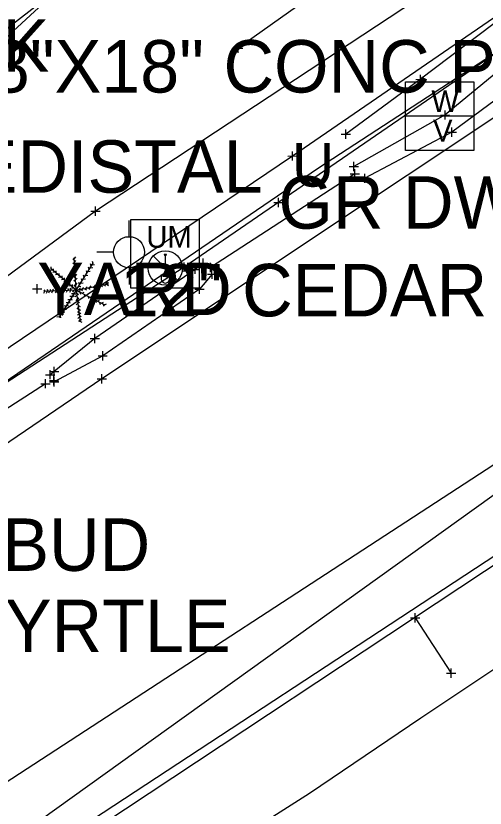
# Model space of a CAD drawing. Extents: x -1 to 1157254, y -1 to 2021979.
# Drawn here: x 1150616.3 to 1150680.9, y 2019818.7 to 2019927.5 of the extents above; entities that cross this region are included whole.
import ezdxf

# ---------------------------------------------------------------- set-up
doc = ezdxf.new("R2010")
doc.units = 0
for name, color, linetype in [('S_BUILDING_ANNOT', 7, 'Continuous'), ('S_CAL_CORNER', 7, 'Continuous'), ('S_CAL_CORNER_ANNOT', 7, 'Continuous'), ('S_CATCH_BASIN', 7, 'Continuous'), ('S_CONTOUR_ANNOT', 7, 'Continuous'), ('S_CONTOUR_MAJOR', 7, 'Continuous'), ('S_CONTOUR_MINOR', 7, 'Continuous'), ('S_CTL_TABLE', 7, 'Continuous'), ('S_CURB', 7, 'Continuous'), ('S_DRIVEWAY_ANNOT', 7, 'Continuous'), ('S_DROP_INLET', 7, 'Continuous'), ('S_DROP_INLET_ANNOT', 7, 'Continuous'), ('S_DTM_PAVEMENT', 7, 'Continuous'), ('S_EDGE_BITUMINOUS_ANNOT', 7, 'Continuous'), ('S_FENCE', 7, 'Continuous'), ('S_GAS_PUMP_ISLAND_ANNOT', 7, 'Continuous'), ('S_GATE', 7, 'Continuous'), ('S_GATE_ANNOT', 7, 'Continuous')]:
    doc.layers.add(name, color=color, linetype=linetype)

msp = doc.modelspace()

# ---------------------------------------------------------------- linework, layer by layer
at = {"layer": 'S_BUILDING_ANNOT'}
for p, q in [((1150674.7, 2019913.87), (1150675.97, 2019913.88)), ((1150675.34, 2019913.24), (1150675.33, 2019914.51)), ((1150675.33, 2019913.88), (1150675.33, 2019913.88)), ((1150676.27, 2019910.87), (1150676.27, 2019912.14)), ((1150675.63, 2019911.51), (1150676.91, 2019911.51)), ((1150676.27, 2019911.51), (1150676.27, 2019911.51)), ((1150654.37, 2019907.61), (1150654.36, 2019908.88)), ((1150653.73, 2019908.24), (1150655, 2019908.25)), ((1150654.37, 2019908.24), (1150654.37, 2019908.24)), ((1150662.79, 2019906.17), (1150662.78, 2019907.44)), ((1150662.15, 2019906.81), (1150663.42, 2019906.81)), ((1150662.78, 2019906.81), (1150662.78, 2019906.81)), ((1150662.93, 2019905.14), (1150662.93, 2019906.42)), ((1150662.3, 2019905.78), (1150663.57, 2019905.78)), ((1150662.93, 2019905.78), (1150662.93, 2019905.78)), ((1150663.66, 2019905.17), (1150664.93, 2019905.18)), ((1150664.3, 2019904.54), (1150664.29, 2019905.81)), ((1150664.29, 2019905.18), (1150664.29, 2019905.18)), ((1150652.45, 2019901.24), (1150652.44, 2019902.51)), ((1150627.27, 2019900.02), (1150627.27, 2019901.29)), ((1150651.81, 2019901.87), (1150653.08, 2019901.88)), ((1150652.44, 2019901.87), (1150652.44, 2019901.87)), ((1150626.64, 2019900.66), (1150627.91, 2019900.66)), ((1150627.27, 2019900.66), (1150627.27, 2019900.66)), ((1150639.49, 2019892.36), (1150639.49, 2019893.64)), ((1150640.97, 2019892.05), (1150640.96, 2019893.32)), ((1150641.43, 2019893.52), (1150642.71, 2019893.52)), ((1150642.07, 2019892.88), (1150642.07, 2019894.15)), ((1150642.07, 2019893.52), (1150642.07, 2019893.52)), ((1150643.07, 2019892.29), (1150643.07, 2019893.56)), ((1150638.85, 2019893), (1150640.13, 2019893)), ((1150639.49, 2019893), (1150639.49, 2019893)), ((1150640.33, 2019892.68), (1150641.6, 2019892.68)), ((1150640.96, 2019892.68), (1150640.96, 2019892.68)), ((1150642.43, 2019892.93), (1150643.7, 2019892.93)), ((1150643.07, 2019892.93), (1150643.07, 2019892.93)), ((1150643.3, 2019891.37), (1150643.29, 2019892.64)), ((1150642.66, 2019892.01), (1150643.93, 2019892.01)), ((1150643.3, 2019892.01), (1150643.3, 2019892.01)), ((1150618.62, 2019890), (1150619.9, 2019890)), ((1150619.26, 2019889.37), (1150619.26, 2019890.64)), ((1150619.26, 2019890), (1150619.26, 2019890)), ((1150640.93, 2019889.97), (1150642.21, 2019889.98)), ((1150641.57, 2019889.34), (1150641.57, 2019890.61)), ((1150641.57, 2019889.97), (1150641.57, 2019889.97)), ((1150627.18, 2019882.56), (1150627.18, 2019883.83)), ((1150626.54, 2019883.2), (1150627.81, 2019883.2)), ((1150627.18, 2019883.2), (1150627.18, 2019883.2)), ((1150628.27, 2019880.18), (1150628.27, 2019881.46)), ((1150627.63, 2019880.82), (1150628.9, 2019880.82)), ((1150628.27, 2019880.82), (1150628.27, 2019880.82)), ((1150621.58, 2019878.03), (1150621.58, 2019879.3)), ((1150620.4, 2019878.22), (1150621.68, 2019878.22)), ((1150620.94, 2019878.66), (1150622.22, 2019878.67)), ((1150621.04, 2019877.59), (1150621.04, 2019878.86)), ((1150621.04, 2019878.22), (1150621.04, 2019878.22)), ((1150621.57, 2019876.79), (1150621.56, 2019878.06)), ((1150621.58, 2019878.67), (1150621.58, 2019878.67)), ((1150628.16, 2019877.01), (1150628.15, 2019878.28)), ((1150619.78, 2019876.98), (1150621.05, 2019876.98)), ((1150620.42, 2019876.35), (1150620.41, 2019877.62)), ((1150620.42, 2019876.98), (1150620.42, 2019876.98)), ((1150620.93, 2019877.42), (1150622.2, 2019877.43)), ((1150620.95, 2019877.26), (1150622.23, 2019877.26)), ((1150621.57, 2019877.42), (1150621.57, 2019877.42)), ((1150621.59, 2019876.62), (1150621.59, 2019877.9)), ((1150621.59, 2019877.26), (1150621.59, 2019877.26)), ((1150627.52, 2019877.64), (1150628.79, 2019877.65)), ((1150628.16, 2019877.65), (1150628.16, 2019877.65)), ((1150671.22, 2019844.21), (1150671.21, 2019845.48)), ((1150670.58, 2019844.84), (1150671.85, 2019844.85)), ((1150671.22, 2019844.85), (1150671.22, 2019844.85)), ((1150676.19, 2019836.6), (1150676.19, 2019837.87)), ((1150675.55, 2019837.24), (1150676.82, 2019837.24)), ((1150676.19, 2019837.24), (1150676.19, 2019837.24))]:
    msp.add_line(p, q, dxfattribs=at)
at = {"layer": 'S_CAL_CORNER'}
for p, q in [((1150635.22, 2019894.53), (1150638.56, 2019891.19)), ((1150636.73, 2019894.75), (1150637.05, 2019894.75)), ((1150636.89, 2019892.86), (1150636.89, 2019894.6)), ((1150636.89, 2019892.86), (1150636.89, 2019891.81)), ((1150636.29, 2019891.96), (1150636.29, 2019891.78)), ((1150637.49, 2019891.96), (1150637.49, 2019891.74))]:
    msp.add_line(p, q, dxfattribs=at)
msp.add_lwpolyline([(1150632.12, 2019899.52), (1150641.54, 2019899.52), (1150641.54, 2019890.11), (1150632.12, 2019890.11)], close=True, dxfattribs=at)
msp.add_circle((1150636.89, 2019892.86), 2.36, dxfattribs=at)
for centre, radius, start, end in [((1150636.89, 2019894.75), 0.156, 180, 0), ((1150636.71, 2019892.36), 0.58, 223.1344, 287.472), ((1150637.06, 2019892.36), 0.58, 252.528, 316.8656)]:
    msp.add_arc(centre, radius, start, end, dxfattribs=at)
msp.add_ellipse((1150636.89, 2019891.62), major_axis=(0, -0.82), ratio=0.744362, start_param=4.519801, end_param=8.000179, dxfattribs=at)
at = {"layer": 'S_CAL_CORNER_ANNOT'}
for points in [[(1150827.62, 2020008.19), (1150733.09, 2019947.48), (1150628.16, 2019877.65), (1150500.75, 2019790.99), (1150424.78, 2019737.67), (1150355.4, 2019749.66)], [(1150682.05, 2019865.85), (1150601.54, 2019813.47), (1150510.58, 2019743.97), (1150405.28, 2019665.92), (1150310.69, 2019593.56), (1150188.92, 2019499.64), (1150039.45, 2019388.15), (1149962.15, 2019331.17), (1149944.63, 2019319.08), (1149774.15, 2019191.52), (1149712.73, 2019145.6), (1149665.81, 2019108.74), (1149605.46, 2019057.66), (1149527.46, 2018983.58), (1149450.12, 2018902.93), (1149278.32, 2018738.82), (1149257.2, 2018716.38), (1149237.23, 2018691.25), (1149165.09, 2018617.77), (1149125.26, 2018579.57), (1149069.5, 2018523.84), (1149012.03, 2018473.77), (1148938.88, 2018408.55)]]:
    msp.add_lwpolyline(points, dxfattribs=at)
at = {"layer": 'S_CATCH_BASIN'}
for p, q in [((1150631.89, 2019897.15), (1150631.89, 2019899.39)), ((1150629.79, 2019895.02), (1150627.47, 2019895.02)), ((1150631.96, 2019890.6), (1150631.96, 2019892.93))]:
    msp.add_line(p, q, dxfattribs=at)
msp.add_circle((1150631.89, 2019895.04), 2.13, dxfattribs=at)
at = {"layer": 'S_CONTOUR_ANNOT'}
for p, q in [((1150669.9, 2019918.44), (1150679.31, 2019918.44)), ((1150669.9, 2019909.02), (1150669.9, 2019918.44)), ((1150679.31, 2019918.44), (1150679.31, 2019909.02)), ((1150669.9, 2019913.75), (1150679.31, 2019913.75)), ((1150679.31, 2019909.02), (1150669.9, 2019909.02))]:
    msp.add_line(p, q, dxfattribs=at)
for points in [[(1150857.08, 2020031.73), (1150832.22, 2020016.43), (1150747.37, 2019963.08), (1150692.94, 2019929.63), (1150639.49, 2019893), (1150583.9, 2019856.96), (1150484.25, 2019790.85), (1150433.08, 2019750.74), (1150355.8, 2019695.65), (1150341.28, 2019681.73), (1150287.94, 2019641.18), (1150216.41, 2019587.25), (1150034.4, 2019445.88), (1149979.98, 2019405.6), (1149934.92, 2019374.11), (1149784.56, 2019258.12)], [(1150776.08, 2020000.06), (1150711.77, 2019956.26), (1150627.27, 2019900.66), (1150578.77, 2019864.96), (1150479.12, 2019798.68), (1150423.47, 2019764.16), (1150358.5, 2019722.73), (1150313.96, 2019690.01), (1150273.95, 2019661.03), (1150225.64, 2019623.26), (1150033.5, 2019468.9), (1149971.69, 2019423.78), (1149931.59, 2019393.98), (1149688.42, 2019230.92)]]:
    msp.add_lwpolyline(points, dxfattribs=at)
at = {"layer": 'S_CONTOUR_MINOR'}
msp.add_lwpolyline([(1150622.8, 2019931.71), (1150421.67, 2019776.18)], dxfattribs=at)
at = {"layer": 'S_CTL_TABLE'}
for p, q in [((1150646.88, 2019922.42), (1150646.88, 2019923.7)), ((1150646.25, 2019923.06), (1150647.52, 2019923.06)), ((1150646.88, 2019923.06), (1150646.88, 2019923.06)), ((1150671.94, 2019918.14), (1150671.94, 2019919.41)), ((1150671.3, 2019918.77), (1150672.58, 2019918.78)), ((1150671.94, 2019918.78), (1150671.94, 2019918.78)), ((1150661.69, 2019910.6), (1150661.69, 2019911.88)), ((1150661.05, 2019911.24), (1150662.33, 2019911.24)), ((1150661.69, 2019911.24), (1150661.69, 2019911.24))]:
    msp.add_line(p, q, dxfattribs=at)
at = {"layer": 'S_CURB'}
for p, q in [((1150624.37, 2019894.16), (1150624.56, 2019894.39)), ((1150624.37, 2019893.91), (1150624.15, 2019894.11)), ((1150624.41, 2019893.35), (1150624.18, 2019893.55)), ((1150624.63, 2019889.83), (1150624.36, 2019894.27)), ((1150624.4, 2019893.68), (1150624.59, 2019893.92)), ((1150624.43, 2019893.08), (1150624.62, 2019893.32)), ((1150624.63, 2019889.83), (1150626.97, 2019893.52)), ((1150626.7, 2019893.14), (1150626.61, 2019893.43)), ((1150626.83, 2019893.3), (1150627.13, 2019893.35)), ((1150626.94, 2019893.48), (1150626.85, 2019893.77)), ((1150621.35, 2019892.57), (1150621.05, 2019892.53)), ((1150624.63, 2019889.83), (1150621.16, 2019892.74)), ((1150621.2, 2019892.72), (1150621.2, 2019893.02)), ((1150621.69, 2019892.3), (1150621.39, 2019892.27)), ((1150621.52, 2019892.47), (1150621.52, 2019892.77)), ((1150621.87, 2019892.17), (1150621.87, 2019892.47)), ((1150622.29, 2019891.81), (1150622.29, 2019892.11)), ((1150624.43, 2019892.77), (1150624.21, 2019892.97)), ((1150624.46, 2019892.12), (1150624.24, 2019892.32)), ((1150624.47, 2019892.37), (1150624.66, 2019892.61)), ((1150626.11, 2019892.17), (1150626.02, 2019892.46)), ((1150626.27, 2019892.39), (1150626.56, 2019892.43)), ((1150626.4, 2019892.69), (1150626.31, 2019892.98)), ((1150626.59, 2019892.88), (1150626.89, 2019892.92)), ((1150622.05, 2019891.98), (1150621.76, 2019891.95)), ((1150622.51, 2019891.6), (1150622.21, 2019891.58)), ((1150622.87, 2019891.27), (1150622.58, 2019891.25)), ((1150622.7, 2019891.48), (1150622.7, 2019891.78)), ((1150623.02, 2019891.2), (1150623.02, 2019891.5)), ((1150623.39, 2019890.9), (1150623.39, 2019891.2)), ((1150624.5, 2019891.52), (1150624.27, 2019891.72)), ((1150624.54, 2019890.96), (1150624.31, 2019891.15)), ((1150624.53, 2019891.81), (1150624.72, 2019892.04)), ((1150624.55, 2019891.24), (1150624.74, 2019891.47)), ((1150625.43, 2019891.12), (1150625.35, 2019891.4)), ((1150625.6, 2019891.33), (1150625.89, 2019891.37)), ((1150625.73, 2019891.61), (1150625.64, 2019891.89)), ((1150625.94, 2019891.85), (1150626.24, 2019891.89)), ((1150621.6, 2019889.7), (1150621.43, 2019889.94)), ((1150622.17, 2019889.71), (1150622, 2019889.96)), ((1150622.72, 2019889.75), (1150622.55, 2019890)), ((1150623.21, 2019891.01), (1150622.91, 2019890.98)), ((1150623.2, 2019889.76), (1150623.03, 2019890.01)), ((1150623.55, 2019890.71), (1150623.25, 2019890.69)), ((1150623.64, 2019889.8), (1150623.47, 2019890.05)), ((1150623.92, 2019890.41), (1150623.62, 2019890.39)), ((1150623.76, 2019890.59), (1150623.76, 2019890.89)), ((1150623.97, 2019889.84), (1150623.8, 2019890.09)), ((1150624.28, 2019890.12), (1150623.98, 2019890.09)), ((1150624.11, 2019890.28), (1150624.11, 2019890.58)), ((1150624.55, 2019890.34), (1150624.33, 2019890.54)), ((1150624.57, 2019890.57), (1150624.76, 2019890.8)), ((1150624.63, 2019889.83), (1150629.05, 2019890.7)), ((1150625.07, 2019890.59), (1150624.98, 2019890.87)), ((1150624.98, 2019890.32), (1150625.27, 2019890.37)), ((1150625, 2019889.92), (1150625.21, 2019890.14)), ((1150625.25, 2019889.95), (1150625.5, 2019889.79)), ((1150625.26, 2019890.79), (1150625.56, 2019890.83)), ((1150625.4, 2019889.98), (1150625.61, 2019890.2)), ((1150625.76, 2019890.03), (1150626.02, 2019889.87)), ((1150625.93, 2019890.08), (1150626.13, 2019890.3)), ((1150626.28, 2019890.14), (1150626.53, 2019889.98)), ((1150626.5, 2019890.21), (1150626.7, 2019890.43)), ((1150626.89, 2019890.27), (1150627.14, 2019890.11)), ((1150627.13, 2019890.35), (1150627.33, 2019890.57)), ((1150627.47, 2019890.38), (1150627.72, 2019890.22)), ((1150627.73, 2019890.44), (1150627.93, 2019890.66)), ((1150627.98, 2019890.49), (1150628.23, 2019890.33)), ((1150628.21, 2019890.54), (1150628.41, 2019890.77)), ((1150628.4, 2019890.58), (1150628.65, 2019890.42)), ((1150628.65, 2019890.63), (1150628.86, 2019890.86)), ((1150628.81, 2019890.64), (1150629.06, 2019890.48)), ((1150628.88, 2019890.69), (1150629.08, 2019890.91)), ((1150620.26, 2019889.62), (1150620.13, 2019889.35)), ((1150624.63, 2019889.83), (1150620.18, 2019889.62)), ((1150620.41, 2019889.64), (1150620.24, 2019889.89)), ((1150620.61, 2019889.65), (1150620.48, 2019889.38)), ((1150620.8, 2019889.67), (1150620.63, 2019889.92)), ((1150620.95, 2019889.67), (1150620.82, 2019889.4)), ((1150621.2, 2019889.67), (1150621.03, 2019889.92)), ((1150621.37, 2019889.68), (1150621.24, 2019889.41)), ((1150621.88, 2019889.7), (1150621.75, 2019889.44)), ((1150624.63, 2019889.83), (1150622.25, 2019886.06)), ((1150622.44, 2019889.73), (1150622.31, 2019889.46)), ((1150622.93, 2019889.75), (1150622.79, 2019889.48)), ((1150623.4, 2019889.78), (1150623.26, 2019889.51)), ((1150623.85, 2019889.78), (1150623.72, 2019889.51)), ((1150624.06, 2019888.97), (1150623.76, 2019888.94)), ((1150624.3, 2019889.34), (1150624, 2019889.3)), ((1150624.24, 2019889.8), (1150624.11, 2019889.53)), ((1150624.21, 2019889.18), (1150624.28, 2019888.89)), ((1150624.42, 2019889.51), (1150624.5, 2019889.22)), ((1150624.69, 2019889.16), (1150624.49, 2019888.93)), ((1150624.63, 2019889.83), (1150628.54, 2019887.79)), ((1150624.63, 2019889.83), (1150625.16, 2019885.46)), ((1150624.71, 2019889.41), (1150624.96, 2019889.25)), ((1150624.74, 2019888.85), (1150625, 2019888.7)), ((1150624.96, 2019889.65), (1150625.22, 2019889.79)), ((1150625.14, 2019889.56), (1150625.21, 2019889.27)), ((1150625.43, 2019889.43), (1150625.7, 2019889.57)), ((1150625.72, 2019889.25), (1150625.79, 2019888.96)), ((1150625.99, 2019889.12), (1150626.25, 2019889.26)), ((1150626.25, 2019888.98), (1150626.32, 2019888.68)), ((1150626.54, 2019888.84), (1150626.81, 2019888.98)), ((1150623.53, 2019888.11), (1150623.23, 2019888.07)), ((1150623.42, 2019887.9), (1150623.49, 2019887.61)), ((1150623.78, 2019888.52), (1150623.49, 2019888.49)), ((1150623.67, 2019888.32), (1150623.75, 2019888.03)), ((1150623.93, 2019888.74), (1150624.01, 2019888.45)), ((1150624.75, 2019888.58), (1150624.56, 2019888.35)), ((1150624.84, 2019888.02), (1150624.64, 2019887.79)), ((1150624.83, 2019888.29), (1150625.08, 2019888.13)), ((1150626.78, 2019888.71), (1150626.85, 2019888.41)), ((1150627.03, 2019888.58), (1150627.29, 2019888.72)), ((1150627.31, 2019888.41), (1150627.38, 2019888.12)), ((1150627.56, 2019888.31), (1150627.83, 2019888.45)), ((1150627.83, 2019888.15), (1150627.9, 2019887.86)), ((1150628.11, 2019888.03), (1150628.38, 2019888.17)), ((1150628.32, 2019887.9), (1150628.39, 2019887.61)), ((1150628.5, 2019887.83), (1150628.77, 2019887.97)), ((1150622.73, 2019886.86), (1150622.43, 2019886.83)), ((1150622.97, 2019887.23), (1150622.67, 2019887.2)), ((1150622.89, 2019887.05), (1150622.96, 2019886.76)), ((1150623.27, 2019887.69), (1150622.97, 2019887.65)), ((1150623.13, 2019887.43), (1150623.21, 2019887.14)), ((1150624.91, 2019887.45), (1150624.71, 2019887.22)), ((1150624.97, 2019886.99), (1150624.78, 2019886.76)), ((1150624.89, 2019887.74), (1150625.15, 2019887.58)), ((1150624.96, 2019887.23), (1150625.22, 2019887.07)), ((1150625, 2019886.8), (1150625.25, 2019886.64)), ((1150622.28, 2019886.15), (1150621.98, 2019886.11)), ((1150622.48, 2019886.45), (1150622.18, 2019886.41)), ((1150622.4, 2019886.31), (1150622.48, 2019886.02)), ((1150622.63, 2019886.65), (1150622.7, 2019886.36)), ((1150625.01, 2019886.61), (1150624.82, 2019886.38)), ((1150625.07, 2019886.17), (1150624.87, 2019885.94)), ((1150625.12, 2019885.75), (1150624.92, 2019885.52)), ((1150625.04, 2019886.39), (1150625.3, 2019886.23)), ((1150625.11, 2019885.93), (1150625.36, 2019885.77)), ((1150625.14, 2019885.58), (1150625.4, 2019885.43))]:
    msp.add_line(p, q, dxfattribs=at)
at = {"layer": 'S_DRIVEWAY_ANNOT'}
for points in [[(1150855.79, 2020029.67), (1150831.35, 2020015.2), (1150787.83, 2019987.87), (1150747.94, 2019962.05), (1150731.32, 2019950.7), (1150693.75, 2019928.98), (1150675.33, 2019913.88), (1150662.78, 2019906.81)], [(1150856.47, 2020028.31), (1150832.96, 2020013.32), (1150788.5, 2019986.18), (1150749.93, 2019959.55), (1150733, 2019948.71), (1150695.21, 2019925.46), (1150676.27, 2019911.51), (1150664.29, 2019905.18)], [(1150642.07, 2019893.52), (1150640.96, 2019892.68), (1150627.18, 2019883.2), (1150621.58, 2019878.67), (1150621.04, 2019878.22)], [(1150643.3, 2019892.01), (1150641.57, 2019889.97), (1150628.27, 2019880.82), (1150621.59, 2019877.26), (1150621.57, 2019877.42)]]:
    msp.add_lwpolyline(points, dxfattribs=at)
at = {"layer": 'S_DROP_INLET'}
for points in [[(1150831.49, 2020022.11), (1150729.58, 2019954.73), (1150690.81, 2019927.93), (1150657.92, 2019906.59), (1150452.8, 2019766.7), (1150415.16, 2019745.86)], [(1150852.18, 2019973.05), (1150778.54, 2019928.45), (1150770.16, 2019919.18), (1150703.8, 2019877.29), (1150608.63, 2019809.12), (1150513.43, 2019739.89), (1150405.92, 2019663.65), (1150352.2, 2019622.72), (1150343.81, 2019614.74), (1150336.72, 2019606.98), (1150314.89, 2019591.84), (1150193.25, 2019498.28), (1150112.69, 2019435.49), (1150059.59, 2019406.16), (1150037.88, 2019389.79), (1149962.99, 2019329.91), (1149914.05, 2019297.4), (1149863.26, 2019256.98)], [(1150853.56, 2019969.99), (1150781.71, 2019924.44), (1150774.41, 2019914.43), (1150697.13, 2019863.12), (1150609.24, 2019805.57), (1150516.58, 2019735.98), (1150408.74, 2019655.56), (1150359.48, 2019622.09), (1150352.77, 2019615.32), (1150355.2, 2019603.6), (1150359.35, 2019593.87)]]:
    msp.add_lwpolyline(points, dxfattribs=at)
at = {"layer": 'S_DROP_INLET_ANNOT'}
for points in [[(1150662.93, 2019905.78), (1150643.07, 2019892.93)], [(1150620.42, 2019876.98), (1150600.25, 2019864)]]:
    msp.add_lwpolyline(points, dxfattribs=at)
at = {"layer": 'S_DTM_PAVEMENT'}
msp.add_lwpolyline([(1150671.22, 2019844.85), (1150676.19, 2019837.24)], dxfattribs=at)
at = {"layer": 'S_EDGE_BITUMINOUS_ANNOT'}
for points in [[(1150780.18, 2020046.65), (1150731.01, 2020016.6), (1150711.37, 2019980.59), (1150665.89, 2019975.73), (1150652.68, 2019953.36), (1150630.56, 2019938.88), (1150601.87, 2019912.49)], [(1150789.87, 2020023.58), (1150749.39, 2019989.07), (1150720.66, 2019965.01), (1150679.31, 2019951.64), (1150664.04, 2019935.25), (1150646.88, 2019923.06)], [(1150798.77, 2020003.69), (1150757.39, 2019975.96), (1150726.02, 2019955.41), (1150691.87, 2019933.84), (1150671.94, 2019918.78), (1150661.69, 2019911.24)]]:
    msp.add_lwpolyline(points, dxfattribs=at)
at = {"layer": 'S_FENCE'}
for points in [[(1150830.5, 2020023.61), (1150689.74, 2019932.52), (1150654.37, 2019908.24), (1150454.61, 2019773.54), (1150421.5, 2019756.1), (1150406.6, 2019759.37)], [(1150775.16, 2019913.88), (1150697.15, 2019862.05), (1150611.54, 2019805.47), (1150516.86, 2019735.37), (1150402.98, 2019659.79), (1150352.98, 2019622.15), (1150350.25, 2019606.72), (1150331.34, 2019598.55), (1150196.24, 2019490.87), (1150043.62, 2019380.11), (1149966.77, 2019324.72), (1149934.21, 2019308.48), (1149916.33, 2019289.12), (1149866.68, 2019250.91)]]:
    msp.add_lwpolyline(points, dxfattribs=at)
at = {"layer": 'S_GAS_PUMP_ISLAND_ANNOT'}
msp.add_lwpolyline([(1150475.18, 2019729.75), (1150486.94, 2019739.18), (1150527.36, 2019744.97), (1150530.87, 2019745.39), (1150533.26, 2019748.12), (1150533.67, 2019750.16), (1150547.31, 2019784.88), (1150559.34, 2019793.54), (1150571.53, 2019802.29), (1150616.62, 2019786.84), (1150617.46, 2019781.87), (1150618.41, 2019777.23), (1150619.34, 2019771.87), (1150620.18, 2019766.9), (1150620.46, 2019766.99), (1150620.64, 2019767.04), (1150619.8, 2019772.01), (1150645.46, 2019813.87), (1150647.12, 2019814.66), (1150656.68, 2019820.74), (1150672.01, 2019831.09), (1150695.8, 2019846.94)], dxfattribs=at)

# ---------------------------------------------------------------- texts
at = {"layer": 'S_CAL_CORNER'}
msp.add_text('UM', height=2.999, dxfattribs=at).set_placement((1150634.27, 2019895.64))
at = {"layer": 'S_CONTOUR_ANNOT'}
for s, p in [('W', (1150673.45, 2019914.28)), ('V', (1150673.68, 2019910.22))]:
    msp.add_text(s, height=3, dxfattribs=at).set_placement(p)
at = {"layer": 'S_CONTOUR_MAJOR'}
msp.add_text('U', height=6, dxfattribs=at).set_placement((1150654.29, 2019904.04))
at = {"layer": 'S_GATE'}
for s, p in [('CONC PK', (1150577.07, 2019919.81)), ('3\'X18"X18" CONC PEDISTAL', (1150593.91, 2019916.96)), ('CONC PEDISTAL', (1150572.68, 2019903.2)), ('GR DW', (1150652.44, 2019898.27)), ('YARD', (1150619.26, 2019886.4))]:
    msp.add_text(s, height=7.2, dxfattribs=at).set_placement(p)
at = {"layer": 'S_GATE_ANNOT'}
for s, p in [('12" CEDAR', (1150630.63, 2019886.23)), ('4" RED BUD', (1150580.02, 2019851.28)), ('2" CREPE MYRTLE', (1150559.5, 2019840.13))]:
    msp.add_text(s, height=7.2, dxfattribs=at).set_placement(p)

doc.saveas('drawing.dxf')
